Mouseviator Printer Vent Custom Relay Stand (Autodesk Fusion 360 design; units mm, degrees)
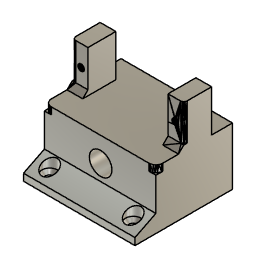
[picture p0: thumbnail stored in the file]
base_mesh_feature "Base Mesh Feature"
convert_mesh "Convert Mesh" bodies "Relay Main Support structure"
delete_face "DeleteFace1"
delete_face "DeleteFace2"
delete_face "DeleteFace3"
delete_face "DeleteFace4"
delete_face "DeleteFace5"
delete_face "DeleteFace6"
delete_face "DeleteFace7"
delete_face "DeleteFace8"
delete_face "DeleteFace9"
delete_face "DeleteFace10"
delete_face "DeleteFace11"
extrude "Extrude1" add of existing geometry blind 4.5
sketch "Sketch2" plane through (0, 169.8371, 0) normal (0, -1, 0) x axis (1, 0, 0)
  line L1 (80.8569, 10) -> (80.8569, 12)
  line L2 (78.8569, 10) -> (80.8569, 10)
  line L3 (78.8569, -4.5) -> (78.8569, 10)
  line L4 (110.8569, -4.5) -> (78.8569, -4.5)
  line L5 (110.8569, 10) -> (110.8569, -4.5)
  line L6 (108.8569, 10) -> (110.8569, 10)
  line L7 (108.8569, 12) -> (108.8569, 10)
  line L8 (80.8569, 12) -> (108.8569, 12)
  line L9 (110.8569, -4.5) -> (78.8569, -4.5)
  line L10 (110.8569, 0.5) -> (110.8569, -4.5)
  line L11 (78.8569, 0.5) -> (110.8569, 0.5)
  line L12 (78.8569, -4.5) -> (78.8569, 0.5)
  circle C1 centre (95, 5) radius 1.7
  point P5 (78.8569, -4.5)
  point P10 (78.8569, -4.5)
  point P13 (78.8569, 0.5)
  horizontal L9
  vertical L10
  horizontal L11
  vertical L12
  coincident P5 P10
  dimension "d3" distance P10 P13 = 5
  dimension "M3_d" diameter C1 = 3.4
extrude "Extrude2" add sketch "Sketch2" profile of L3 L4 L5 L9 L10 L11 L12 along normal blind 6
chamfer "Chamfer1" distance 3 distance 6
work_plane "WorkPlane1" AlongDistance -2
work_plane "WorkPlane2" AlongDistance -13
sketch "Sketch3" plane through (0, 178.8371, 0) normal (0, 1, 0) x axis (1, 0, 0)
  circle C1 centre (95, -5) radius 1.7
hole "Hole1" HoleDepth 13 HoleDiameter 3.4 TipAngle 118 CBDepth 3 CBDiameter 6.5
extrude "Extrude3" cut of existing geometry blind -9
sketch "Sketch4" plane through (0, 0, -2.5) normal (0, 0, -1) x axis (-1, 0, 0)
  line L1 (-110.8569, 163.8371) -> (-78.8569, 163.8371)
  line L2 (-78.8569, 163.8371) -> (-78.8569, 169.8371)
  circle C1 centre (-82.8569, 167.3371) radius 1.2
  circle C2 centre (-106.8569, 167.3371) radius 1.2
  circle C3 centre (-82.8569, 167.3371) radius 2.2
  circle C4 centre (-106.8569, 167.3371) radius 2.2
  point P2 (-82.8569, 167.3371)
  concentric C1 C3
  concentric C2 C4
  dimension "M2_d" diameter C1 = 2.4
  dimension "d19" distance P2 L1 = 3.5
  dimension "d20" distance P2 L2 = 4
  dimension "d21" diameter C2 = 2.4
  dimension "M2_d2" diameter C3 = 4.4
  dimension "d28" diameter C4 = 4.4 (= "M2_d2")
hole "Hole2" HoleDepth 13 HoleDiameter 2.4 TipAngle 118 CSDiameter 4.4 CSAngle 90
extrude "Extrude4" cut sketch "Sketch4" profile of C1 C2 C3 C4 against normal blind 5
named bodies: "Relay Main Support structure"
